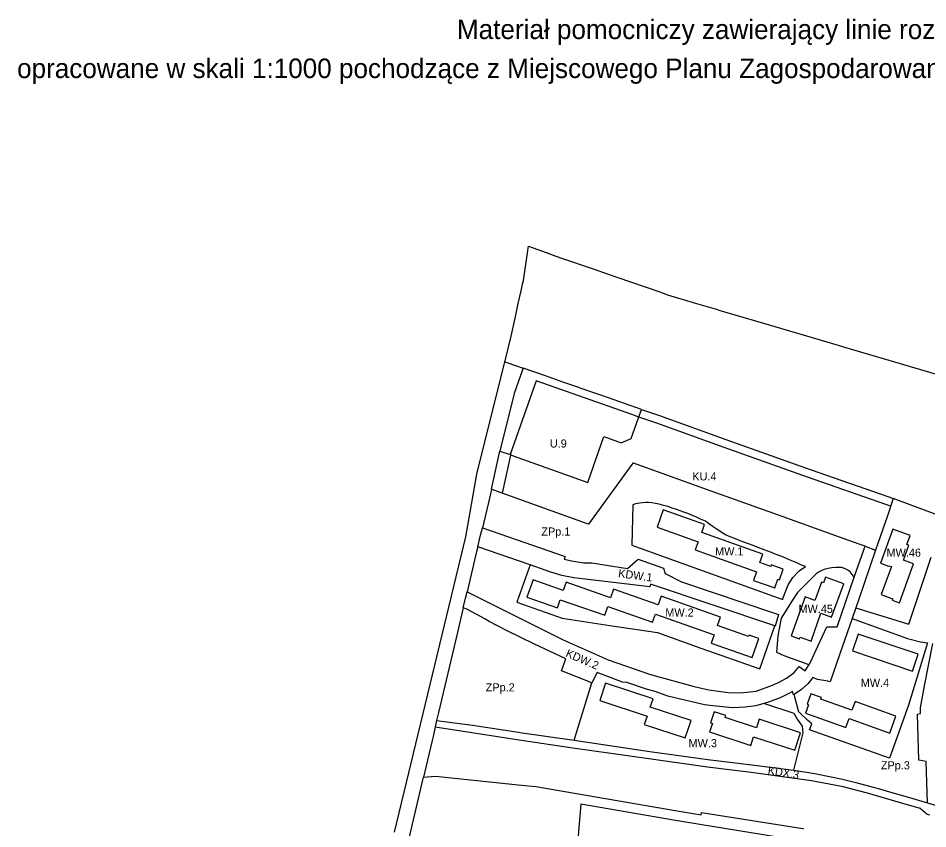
# Model space of a CAD drawing. Extents: x 7424434 to 7425898, y 5541432 to 5542659.
# Drawn here: x 7424434 to 7424994, y 5542160 to 5542659 of the extents above; entities that cross this region are included whole.
import ezdxf

# ---------------------------------------------------------------- set-up
doc = ezdxf.new("R2010")
doc.units = 0
for name, color, linetype in [('info', 7, 'Continuous'), ('linie rozgraniczające', 7, 'Continuous'), ('nieprzekraczalne linie zabudowy', 7, 'Continuous'), ('obowiazujace linie zabudowy', 7, 'Continuous'), ('przeznaczenia terenów', 7, 'Continuous')]:
    doc.layers.add(name, color=color, linetype=linetype)

msp = doc.modelspace()

# ---------------------------------------------------------------- linework, layer by layer
at = {"layer": 'linie rozgraniczające'}
for p, q in [((7424747.58, 5542514.42), (7424748.19, 5542518.62)), ((7424748.19, 5542518.62), (7424759.12, 5542514.54)), ((7424745.11, 5542497.46), (7424747.58, 5542514.42)), ((7424759.12, 5542514.54), (7424765.14, 5542512.45)), ((7424765.14, 5542512.45), (7424769.26, 5542511.04)), ((7424769.26, 5542511.04), (7424787.38, 5542504.79)), ((7424787.38, 5542504.79), (7424802.65, 5542499.52)), ((7424744.59, 5542495.06), (7424745.11, 5542497.46)), ((7424802.65, 5542499.52), (7424828.39, 5542490.65)), ((7424742.01, 5542483.22), (7424743.74, 5542491.15)), ((7424743.74, 5542491.15), (7424744.59, 5542495.06)), ((7424828.39, 5542490.65), (7424833.85, 5542488.62)), ((7424833.85, 5542488.62), (7424851.6, 5542483.34)), ((7424740.46, 5542476.12), (7424742.01, 5542483.22)), ((7424851.6, 5542483.34), (7424864.53, 5542479.49)), ((7424864.53, 5542479.49), (7424865.45, 5542479.21)), ((7424865.45, 5542479.21), (7424880.09, 5542474.94)), ((7424737.62, 5542463.08), (7424740.46, 5542476.12)), ((7424880.09, 5542474.94), (7424892.89, 5542471.2)), ((7424892.89, 5542471.2), (7424938.86, 5542457.56)), ((7424733.85, 5542447.88), (7424737.62, 5542463.08)), ((7424938.86, 5542457.56), (7424942.63, 5542456.45)), ((7424942.63, 5542456.45), (7424970.07, 5542448.41)), ((7424716.59, 5542378.26), (7424733.73, 5542447.39)), ((7424733.73, 5542447.39), (7424733.85, 5542447.88)), ((7424733.73, 5542447.39), (7424734.89, 5542447.02)), ((7424734.89, 5542447.02), (7424744.92, 5542443.52)), ((7424970.07, 5542448.41), (7425002.02, 5542438.91)), ((7424744.92, 5542443.52), (7424743.36, 5542439.03)), ((7424758.82, 5542438.66), (7424744.92, 5542443.52)), ((7424743.36, 5542439.03), (7424739.45, 5542427.79)), ((7424770.06, 5542434.73), (7424758.82, 5542438.66)), ((7424779.86, 5542431.31), (7424770.06, 5542434.73)), ((7424780.13, 5542431.21), (7424779.86, 5542431.31)), ((7424789.77, 5542427.86), (7424780.13, 5542431.21)), ((7424739.45, 5542427.79), (7424730.64, 5542392.38)), ((7424793.37, 5542426.6), (7424789.77, 5542427.86)), ((7424817.89, 5542418.07), (7424793.37, 5542426.6)), ((7424815.99, 5542412.83), (7424817.89, 5542418.07)), ((7424817.89, 5542418.07), (7424828.25, 5542414.47)), ((7424811.43, 5542400.27), (7424815.99, 5542412.83)), ((7424828.25, 5542414.47), (7424870.4, 5542399.4)), ((7424785.06, 5542373.76), (7424794.62, 5542401.34)), ((7424794.62, 5542401.34), (7424805.37, 5542397.43)), ((7424805.37, 5542397.43), (7424811.43, 5542400.27)), ((7424870.4, 5542399.4), (7424921.66, 5542381.02)), ((7424725.5, 5542369.02), (7424730.44, 5542391.58)), ((7424730.44, 5542391.58), (7424730.64, 5542392.38)), ((7424730.64, 5542392.38), (7424736.95, 5542390.25)), ((7424736.95, 5542390.25), (7424738.82, 5542389.58)), ((7424738.82, 5542389.58), (7424784.81, 5542373.04)), ((7424811.93, 5542384.28), (7424785.27, 5542347.42)), ((7424812.5, 5542385.08), (7424811.93, 5542384.28)), ((7424812.83, 5542384.96), (7424812.5, 5542385.08)), ((7424856.25, 5542369.41), (7424812.83, 5542384.96)), ((7424709.76, 5542339.63), (7424716.59, 5542378.26)), ((7424921.66, 5542381.02), (7424969.88, 5542364.28)), ((7424784.81, 5542373.04), (7424785.06, 5542373.76)), ((7424725.45, 5542368.81), (7424724.44, 5542364.19)), ((7424725.5, 5542369.02), (7424725.45, 5542368.81)), ((7424726.97, 5542368.48), (7424725.5, 5542369.02)), ((7424783.28, 5542348.14), (7424726.97, 5542368.48)), ((7424857.86, 5542368.83), (7424856.25, 5542369.41)), ((7424907.78, 5542350.95), (7424857.86, 5542368.83)), ((7424724.44, 5542364.19), (7424719.88, 5542345.25)), ((7424972.7, 5542363.24), (7424969.06, 5542352.6)), ((7424969.88, 5542364.28), (7424972.7, 5542363.24)), ((7425004.03, 5542351.55), (7424972.7, 5542363.24)), ((7424812.37, 5542359.37), (7424811.77, 5542334.52)), ((7424814.16, 5542359.9), (7424812.37, 5542359.37)), ((7424816.52, 5542360.41), (7424814.16, 5542359.9)), ((7424818.72, 5542360.67), (7424816.52, 5542360.41)), ((7424820.18, 5542360.76), (7424818.72, 5542360.67)), ((7424822.13, 5542360.73), (7424820.18, 5542360.76)), ((7424824.06, 5542360.62), (7424822.13, 5542360.73)), ((7424826.51, 5542360.28), (7424824.06, 5542360.62)), ((7424829.49, 5542359.64), (7424826.51, 5542360.28)), ((7424831.39, 5542359.05), (7424829.49, 5542359.64)), ((7424834.2, 5542358.25), (7424831.39, 5542359.05)), ((7424836.72, 5542357.36), (7424834.2, 5542358.25)), ((7424839.25, 5542356.48), (7424836.72, 5542357.36)), ((7424843.76, 5542354.95), (7424839.25, 5542356.48)), ((7424846.29, 5542354.05), (7424843.76, 5542354.95)), ((7424849.15, 5542352.78), (7424846.29, 5542354.05)), ((7424851.65, 5542351.72), (7424849.15, 5542352.78)), ((7424854.05, 5542350.62), (7424851.65, 5542351.72)), ((7424857.18, 5542349.25), (7424854.05, 5542350.62)), ((7424909.4, 5542350.37), (7424907.78, 5542350.95)), ((7424944.75, 5542337.7), (7424909.4, 5542350.37)), ((7424969.06, 5542352.6), (7424961.85, 5542331.57)), ((7424718.8, 5542340.75), (7424719.88, 5542345.25)), ((7424719.88, 5542345.25), (7424730.63, 5542341.51)), ((7424783.33, 5542348.12), (7424783.28, 5542348.14)), ((7424784.29, 5542347.77), (7424783.33, 5542348.12)), ((7424785.27, 5542347.42), (7424784.29, 5542347.77)), ((7424858.23, 5542348.53), (7424857.18, 5542349.25)), ((7424861.32, 5542346.31), (7424858.23, 5542348.53)), ((7424863.82, 5542344.63), (7424861.32, 5542346.31)), ((7424865.34, 5542343.48), (7424863.82, 5542344.63)), ((7424665.78, 5542157.87), (7424709.76, 5542339.63)), ((7424717.07, 5542333.55), (7424718.8, 5542340.75)), ((7424730.63, 5542341.51), (7424765.58, 5542329.35)), ((7424867.43, 5542342.16), (7424865.34, 5542343.48)), ((7424869.5, 5542340.96), (7424867.43, 5542342.16)), ((7424871.42, 5542340), (7424869.5, 5542340.96)), ((7424872.91, 5542339.45), (7424871.42, 5542340)), ((7424875.64, 5542338.43), (7424872.91, 5542339.45)), ((7424717.07, 5542333.55), (7424716.52, 5542331.25)), ((7424749.29, 5542322.4), (7424717.07, 5542333.55)), ((7424811.77, 5542334.52), (7424904.21, 5542301.36)), ((7424878.6, 5542337.31), (7424875.64, 5542338.43)), ((7424883.72, 5542335.35), (7424878.6, 5542337.31)), ((7424886.42, 5542334.35), (7424883.72, 5542335.35)), ((7424889, 5542333.41), (7424886.42, 5542334.35)), ((7424893.31, 5542331.75), (7424889, 5542333.41)), ((7424952.3, 5542335), (7424944.75, 5542337.7)), ((7424954.89, 5542334.07), (7424952.3, 5542335)), ((7424954.51, 5542331.64), (7424955.32, 5542333.92)), ((7424955.32, 5542333.92), (7424954.89, 5542334.07)), ((7424955.32, 5542333.92), (7424961.85, 5542331.57)), ((7424716.38, 5542330.68), (7424710.5, 5542305.82)), ((7424716.52, 5542331.25), (7424716.38, 5542330.68)), ((7424765.58, 5542329.35), (7424770.74, 5542327.55)), ((7424770.74, 5542327.55), (7424770.22, 5542325.99)), ((7424897.77, 5542330.05), (7424893.31, 5542331.75)), ((7424900.1, 5542329.11), (7424897.77, 5542330.05)), ((7424904.08, 5542327.49), (7424900.1, 5542329.11)), ((7424908.95, 5542325.47), (7424904.08, 5542327.49)), ((7424948.74, 5542314.81), (7424954.51, 5542331.64)), ((7424961.85, 5542331.57), (7424951.28, 5542300.72)), ((7424749.29, 5542322.4), (7424741.13, 5542299.47)), ((7424761.92, 5542318.01), (7424749.29, 5542322.4)), ((7424770.22, 5542325.99), (7424774.79, 5542324.89)), ((7424774.79, 5542324.89), (7424782.27, 5542323.72)), ((7424782.27, 5542323.72), (7424787.31, 5542323.7)), ((7424787.31, 5542323.7), (7424809.18, 5542320.26)), ((7424809.18, 5542320.26), (7424815.66, 5542325.84)), ((7424815.66, 5542325.84), (7424831.34, 5542320.35)), ((7424912.71, 5542323.87), (7424908.95, 5542325.47)), ((7424914.19, 5542323.28), (7424912.71, 5542323.87)), ((7424916.31, 5542322.24), (7424914.19, 5542323.28)), ((7424918.72, 5542321.43), (7424916.31, 5542322.24)), ((7424982.33, 5542285.97), (7424995.99, 5542327.25)), ((7424768.75, 5542315.92), (7424761.92, 5542318.01)), ((7424831.34, 5542320.35), (7424832.45, 5542317.04)), ((7424832.45, 5542317.04), (7424842.51, 5542312.06)), ((7424910.81, 5542314.65), (7424914.87, 5542318.8)), ((7424925.23, 5542316.81), (7424913.74, 5542305.44)), ((7424914.87, 5542318.8), (7424918.72, 5542321.43)), ((7424927.03, 5542318.18), (7424925.23, 5542316.81)), ((7424928.28, 5542318.75), (7424927.03, 5542318.18)), ((7424930.22, 5542319.5), (7424928.28, 5542318.75)), ((7424932.68, 5542320.11), (7424930.22, 5542319.5)), ((7424933.67, 5542320.42), (7424932.68, 5542320.11)), ((7424934.96, 5542320.66), (7424933.67, 5542320.42)), ((7424937.35, 5542320.77), (7424934.96, 5542320.66)), ((7424939, 5542320.84), (7424937.35, 5542320.77)), ((7424940.76, 5542320.71), (7424939, 5542320.84)), ((7424942.69, 5542320.13), (7424940.76, 5542320.71)), ((7424944.77, 5542319.17), (7424942.69, 5542320.13)), ((7424946.27, 5542318.18), (7424944.77, 5542319.17)), ((7424948.74, 5542314.81), (7424946.27, 5542318.18)), ((7424776.16, 5542314.52), (7424768.75, 5542315.92)), ((7424786.7, 5542313.19), (7424776.16, 5542314.52)), ((7424822.87, 5542308.89), (7424786.7, 5542313.19)), ((7424842.51, 5542312.06), (7424899.04, 5542292.89)), ((7424908.09, 5542310.13), (7424910.81, 5542314.65)), ((7424938.26, 5542284.22), (7424948.74, 5542314.81)), ((7424709.57, 5542301.88), (7424710.5, 5542305.82)), ((7424710.5, 5542305.82), (7424738.45, 5542291.93)), ((7424823.43, 5542310.56), (7424822.87, 5542308.89)), ((7424899.92, 5542284.87), (7424823.43, 5542310.56)), ((7424904.8, 5542301.67), (7424908.09, 5542310.13)), ((7424913.74, 5542305.44), (7424910.24, 5542300.08)), ((7424708.17, 5542295.94), (7424709.57, 5542301.88)), ((7424741.13, 5542299.47), (7424769.09, 5542289.67)), ((7424910.24, 5542300.08), (7424903.72, 5542289.61)), ((7424904.21, 5542301.36), (7424904.67, 5542301.2)), ((7424904.67, 5542301.2), (7424904.8, 5542301.67)), ((7424951.28, 5542300.72), (7424949.67, 5542296.03)), ((7424708.17, 5542295.94), (7424706.73, 5542289.82)), ((7424710.25, 5542295.16), (7424708.17, 5542295.94)), ((7424721.39, 5542289.12), (7424710.25, 5542295.16)), ((7424949.67, 5542296.03), (7424947.43, 5542289.48)), ((7424949.67, 5542296.03), (7424961.46, 5542292.39)), ((7424706.73, 5542289.82), (7424705.06, 5542282.73)), ((7424724.17, 5542287.61), (7424721.39, 5542289.12)), ((7424738.45, 5542291.93), (7424769.69, 5542276.4)), ((7424769.09, 5542289.67), (7424798.26, 5542285.03)), ((7424899.04, 5542292.89), (7424902.06, 5542291.87)), ((7424902.06, 5542291.87), (7424900.09, 5542284.81)), ((7424903.72, 5542289.61), (7424901.64, 5542278.86)), ((7424947.43, 5542289.48), (7424939.85, 5542267.76)), ((7424947.43, 5542289.48), (7424981.55, 5542277.21)), ((7424961.46, 5542292.39), (7424982.33, 5542285.97)), ((7424705.06, 5542282.73), (7424704.41, 5542279.97)), ((7424734.74, 5542282.13), (7424724.17, 5542287.61)), ((7424798.26, 5542285.03), (7424827.65, 5542280.81)), ((7424890.63, 5542258.42), (7424899.92, 5542284.87)), ((7424900.09, 5542284.81), (7424899.92, 5542284.87)), ((7424926.45, 5542272.78), (7424931.82, 5542284.27)), ((7424931.82, 5542284.27), (7424938.26, 5542284.22)), ((7424704.41, 5542279.97), (7424692.91, 5542231.55)), ((7424751.96, 5542273.59), (7424734.74, 5542282.13)), ((7424827.65, 5542280.81), (7424854.29, 5542271.15)), ((7424901.64, 5542278.86), (7424900.89, 5542268.69)), ((7424981.55, 5542277.21), (7424989.37, 5542275.1)), ((7424771.27, 5542264.57), (7424751.96, 5542273.59)), ((7424769.69, 5542276.4), (7424797.3, 5542264.07)), ((7424921.76, 5542262.51), (7424926.45, 5542272.78)), ((7424993.68, 5542274.53), (7424981.97, 5542236.08)), ((7424989.37, 5542275.1), (7424993.68, 5542274.53)), ((7424991.92, 5542247.99), (7424997.06, 5542274.09)), ((7424854.29, 5542271.15), (7424890.63, 5542258.42)), ((7424900.89, 5542268.69), (7424905.38, 5542266.6)), ((7424905.38, 5542266.6), (7424920.06, 5542261.4)), ((7424939.85, 5542267.76), (7424933.97, 5542250.37)), ((7424768.64, 5542257.3), (7424771.27, 5542264.57)), ((7424797.3, 5542264.07), (7424823.41, 5542255.06)), ((7424918.53, 5542257.14), (7424920.95, 5542261.17)), ((7424920.06, 5542261.4), (7424920.95, 5542261.17)), ((7424920.95, 5542261.17), (7424921.76, 5542262.51)), ((7424787.32, 5542249.76), (7424768.64, 5542257.3)), ((7424790.42, 5542256.29), (7424787.32, 5542249.76)), ((7424806.05, 5542250.28), (7424790.42, 5542256.29)), ((7424823.41, 5542255.06), (7424850.23, 5542247.49)), ((7424907.06, 5542252.81), (7424911.72, 5542256.3)), ((7424911.72, 5542256.3), (7424914.76, 5542259.99)), ((7424914.76, 5542259.99), (7424918.53, 5542257.14)), ((7424776.27, 5542214.49), (7424787.32, 5542249.76)), ((7424808.77, 5542249.97), (7424806.05, 5542250.28)), ((7424821.43, 5542245.84), (7424808.77, 5542249.97)), ((7424898.47, 5542248.36), (7424902.07, 5542249.98)), ((7424902.07, 5542249.98), (7424907.06, 5542252.81)), ((7424920.12, 5542249.27), (7424916.26, 5542245.71)), ((7424923.25, 5542253.07), (7424920.12, 5542249.27)), ((7424926.01, 5542251.91), (7424923.25, 5542253.07)), ((7424932.38, 5542250.93), (7424926.01, 5542251.91)), ((7424933.97, 5542250.37), (7424932.38, 5542250.93)), ((7424826.25, 5542244.46), (7424821.43, 5542245.84)), ((7424834.08, 5542241.6), (7424826.25, 5542244.46)), ((7424850.23, 5542247.49), (7424859.15, 5542245.44)), ((7424859.15, 5542245.44), (7424871.18, 5542243.86)), ((7424871.18, 5542243.86), (7424878.75, 5542243.62)), ((7424878.75, 5542243.62), (7424888.42, 5542244.73)), ((7424888.42, 5542244.73), (7424898.47, 5542248.36)), ((7424909.28, 5542243.6), (7424906.35, 5542242.25)), ((7424910.62, 5542244.53), (7424909.28, 5542243.6)), ((7424911.24, 5542242.4), (7424910.62, 5542244.53)), ((7424916.26, 5542245.71), (7424911.66, 5542242.68)), ((7424989.5, 5542234.42), (7424991.92, 5542247.99)), ((7424856.49, 5542236.32), (7424834.08, 5542241.6)), ((7424903.14, 5542240.71), (7424895.88, 5542237.89)), ((7424906.35, 5542242.25), (7424903.14, 5542240.71)), ((7424911.66, 5542242.68), (7424911.24, 5542242.4)), ((7424914.68, 5542231.77), (7424911.66, 5542242.68)), ((7424863.77, 5542235.49), (7424856.49, 5542236.32)), ((7424873.7, 5542234.51), (7424863.77, 5542235.49)), ((7424881.61, 5542234.81), (7424873.7, 5542234.51)), ((7424888.09, 5542235.78), (7424881.61, 5542234.81)), ((7424892.98, 5542237.1), (7424888.09, 5542235.78)), ((7424895.88, 5542237.89), (7424892.98, 5542237.1)), ((7424911.74, 5542230.97), (7424892.98, 5542237.1)), ((7424981.97, 5542236.08), (7424970.33, 5542203.42)), ((7424989.5, 5542230.98), (7424989.5, 5542234.42)), ((7424692.91, 5542231.55), (7424691.75, 5542226.67)), ((7424913.36, 5542228.15), (7424911.74, 5542230.97)), ((7424913.46, 5542227.99), (7424913.36, 5542228.15)), ((7424913.79, 5542227.41), (7424913.46, 5542227.99)), ((7424916.87, 5542223.11), (7424913.79, 5542227.41)), ((7424915.18, 5542231.4), (7424914.68, 5542231.77)), ((7424919.97, 5542226.91), (7424915.18, 5542231.4)), ((7424922.51, 5542224.54), (7424919.97, 5542226.91)), ((7424987.53, 5542230.58), (7424989.5, 5542230.98)), ((7424988.37, 5542202.28), (7424987.53, 5542230.58)), ((7424690.85, 5542222.85), (7424689.55, 5542216.85)), ((7424691.75, 5542226.67), (7424690.85, 5542222.85)), ((7424690.85, 5542222.85), (7424713.32, 5542219.34)), ((7424691.75, 5542226.67), (7424713.85, 5542223.78)), ((7424713.85, 5542223.78), (7424742.15, 5542219.4)), ((7424917.33, 5542218.98), (7424916.87, 5542223.11)), ((7424921.15, 5542220.87), (7424922.51, 5542224.54)), ((7424689.55, 5542216.85), (7424688.74, 5542213.53)), ((7424713.32, 5542219.34), (7424742.51, 5542214.77)), ((7424742.15, 5542219.4), (7424743.04, 5542219.26)), ((7424743.04, 5542219.26), (7424776.27, 5542214.49)), ((7424911.52, 5542196.1), (7424917.33, 5542218.98)), ((7424970.33, 5542203.42), (7424921.15, 5542220.87)), ((7424688.74, 5542213.53), (7424683.68, 5542191.73)), ((7424742.51, 5542214.77), (7424775.52, 5542209.94)), ((7424775.52, 5542209.94), (7424822.27, 5542203.18)), ((7424776.27, 5542214.49), (7424822.85, 5542207.68)), ((7424822.85, 5542207.68), (7424858.56, 5542202.71)), ((7424822.27, 5542203.18), (7424858.4, 5542198.14)), ((7424858.56, 5542202.71), (7424885.77, 5542199.33)), ((7424885.77, 5542199.33), (7424911.52, 5542196.1)), ((7424993, 5542201.41), (7424988.37, 5542202.28)), ((7424993.72, 5542175.99), (7424993, 5542201.41)), ((7424858.4, 5542198.14), (7424885.22, 5542194.8)), ((7424885.22, 5542194.8), (7424922.46, 5542189.82)), ((7424911.52, 5542196.1), (7424919.35, 5542194.89)), ((7424919.35, 5542194.89), (7424925.55, 5542193.87)), ((7424925.55, 5542193.87), (7424933.46, 5542192.18)), ((7424674.48, 5542152.32), (7424683.68, 5542191.73)), ((7424683.68, 5542191.73), (7424691.14, 5542192.38)), ((7424691.14, 5542192.38), (7424744.06, 5542186.89)), ((7424922.46, 5542189.82), (7424940.84, 5542186.25)), ((7424933.46, 5542192.18), (7424941.37, 5542190.48)), ((7424941.37, 5542190.48), (7424949.74, 5542188.41)), ((7424949.74, 5542188.41), (7424958.1, 5542186.33)), ((7424744.06, 5542186.89), (7424752.69, 5542186)), ((7424752.69, 5542186), (7424839.76, 5542171)), ((7424940.84, 5542186.25), (7424956.55, 5542182.15)), ((7424956.55, 5542182.15), (7424980.38, 5542175.26)), ((7424958.1, 5542186.33), (7424964.24, 5542184.59)), ((7424964.24, 5542184.59), (7424970.37, 5542182.85)), ((7424970.37, 5542182.85), (7424981.19, 5542179.67)), ((7424981.19, 5542179.67), (7424993.72, 5542175.99)), ((7424839.76, 5542171), (7424854.55, 5542168.59)), ((7424980.38, 5542175.26), (7424989.32, 5542172.68)), ((7424989.32, 5542172.68), (7424993.48, 5542169.09)), ((7424993.72, 5542175.99), (7425003.48, 5542173.11)), ((7424854.55, 5542168.59), (7424854.67, 5542169.96)), ((7424854.67, 5542169.96), (7424917.08, 5542160.2)), ((7424993.48, 5542169.09), (7424995.11, 5542168.64)), ((7424917.08, 5542160.2), (7424917.55, 5542159.83))]:
    msp.add_line(p, q, dxfattribs=at)
at = {"layer": 'nieprzekraczalne linie zabudowy'}
for points in [[(7424816.19, 5542413.4), (7424812.45, 5542414.72), (7424752.92, 5542435.68), (7424736.95, 5542390.25)], [(7424970.97, 5542358.55), (7424968.2, 5542359.57), (7424920, 5542376.3), (7424868.72, 5542394.69), (7424826.59, 5542409.75), (7424816.25, 5542413.35)], [(7424737.43, 5542390.68), (7424737.26, 5542389.98), (7424732.14, 5542366.62)]]:
    msp.add_lwpolyline(points, dxfattribs=at)
msp.add_lwpolyline([(7424910.57, 5542153.41), (7424853.59, 5542162.67), (7424838.77, 5542165.08), (7424780.57, 5542175.11), (7424771.38, 5542068.74), (7424791.79, 5542066.66), (7424797.38, 5542066.09), (7424845.66, 5542061.44), (7424898.44, 5542056.38), (7424903.72, 5542105.59)], close=True, dxfattribs=at)
at = {"layer": 'obowiazujace linie zabudowy'}
for points in [[(7424831.13, 5542356.23), (7424827.35, 5542345.62), (7424852.68, 5542336.61), (7424850.9, 5542331.61), (7424888.64, 5542318.19), (7424886.75, 5542312.89), (7424899.82, 5542308.25), (7424901.71, 5542313.57), (7424902.67, 5542313.23), (7424904.99, 5542319.74), (7424897.65, 5542322.35), (7424897.33, 5542321.46), (7424890.69, 5542323.83), (7424892.5, 5542328.94), (7424854.87, 5542342.32), (7424856.62, 5542347.33)], [(7424964.94, 5542323.38), (7424969.75, 5542321.68), (7424969.83, 5542321.92), (7424971.54, 5542321.35), (7424965.25, 5542304.18), (7424971.17, 5542302.01), (7424972.4, 5542301.56), (7424972.07, 5542300.65), (7424976.6, 5542299.03), (7424985.23, 5542323.15), (7424978.94, 5542325.4), (7424982.21, 5542334.54), (7424981.09, 5542334.94), (7424983.07, 5542340.55), (7424972.35, 5542344.34)], [(7424751.07, 5542313.21), (7424747.35, 5542302.59), (7424766.03, 5542296.04), (7424767.78, 5542301.01), (7424795.19, 5542291.4), (7424797.09, 5542296.83), (7424824.59, 5542287.18), (7424826.31, 5542292.08), (7424862.49, 5542279.39), (7424860.67, 5542274.21), (7424885.95, 5542265.34), (7424890.08, 5542277.1), (7424883.96, 5542279.25), (7424883.66, 5542278.39), (7424864.65, 5542285.06), (7424866.48, 5542290.29), (7424829.93, 5542303.12), (7424828.04, 5542297.74), (7424800.53, 5542307.39), (7424798.7, 5542302.16), (7424771.45, 5542311.72), (7424769.67, 5542306.66)], [(7424918.5, 5542302.74), (7424909.84, 5542278.82), (7424914.96, 5542276.97), (7424915.34, 5542278.01), (7424916.55, 5542277.57), (7424922.21, 5542275.52), (7424928.1, 5542292.7), (7424934.76, 5542290.22), (7424942.29, 5542310.85), (7424931.1, 5542314.91), (7424929.78, 5542311.36), (7424928.57, 5542311.75), (7424925.59, 5542303.69), (7424924.46, 5542300.58)], [(7424951.08, 5542279.84), (7424947.57, 5542269.46), (7424984.43, 5542257), (7424987.94, 5542267.38)], [(7424795.71, 5542249.67), (7424792.18, 5542239.03), (7424821.22, 5542229.4), (7424819.53, 5542224.3), (7424844.76, 5542215.93), (7424848.3, 5542226.6), (7424823.23, 5542234.91), (7424824.91, 5542240)], [(7424943.52, 5542222.28), (7424945.51, 5542227.85), (7424970.55, 5542218.92), (7424974.28, 5542229.39), (7424949.16, 5542238.34), (7424947.23, 5542232.92), (7424928.06, 5542239.75), (7424928.46, 5542240.88), (7424922.01, 5542243.17), (7424919.68, 5542236.64), (7424920.62, 5542236.3), (7424918.77, 5542231.1)], [(7424885.03, 5542211.37), (7424886.74, 5542216.6), (7424912.1, 5542208.31), (7424915.65, 5542219.17), (7424890.27, 5542227.47), (7424888.53, 5542222.16), (7424869.33, 5542228.44), (7424869.73, 5542229.67), (7424862.42, 5542232.06), (7424860.18, 5542225.21), (7424861.42, 5542224.81), (7424859.73, 5542219.64)]]:
    msp.add_lwpolyline(points, close=True, dxfattribs=at)

# ---------------------------------------------------------------- texts
at = {"layer": 'info'}
for s, p in [('Materiał pomocniczy zawierający linie rozgraniczające teren o różnym przeznaczeniu i różnych warunkach zagospodarowania terenu, ', (7424704.25, 5542645.97)), ('opracowane w skali 1:1000 pochodzące z Miejscowego Planu Zagospodarowania Przestrzennego obszaru "OSIEDLE KURDWANÓW" zatwierdzonego uchwałą RMK Nr LXXIX/1938/17 z dnia 5 lipca 2017 r.', (7424433.64, 5542621.97))]:
    msp.add_text(s, height=12, dxfattribs=at).set_placement(p)
at = {"layer": 'przeznaczenia terenów'}
for s, p in [('U.9', (7424761.42, 5542394.62)), ('KU.4', (7424849.06, 5542374.4)), ('ZPp.1', (7424756.2, 5542340.43)), ('MW.1', (7424863.05, 5542328.23)), ('MW.46', (7424968.56, 5542327.44)), ('MW.2', (7424832.45, 5542290.59)), ('MW.45', (7424914.39, 5542292.85)), ('ZPp.2', (7424721.96, 5542244.57)), ('MW.4', (7424952.7, 5542247.37)), ('MW.3', (7424846.75, 5542210.24)), ('ZPp.3', (7424965.05, 5542196.59))]:
    msp.add_text(s, height=5, dxfattribs=at).set_placement(p)
for s, rotation, p in [('KDW.1', 352.4712, (7424803.24, 5542314.89)), ('KDW.2', 336.6252, (7424770.71, 5542266.2)), ('KDX.3', 350.9031, (7424895.22, 5542193.66))]:
    msp.add_text(s, height=5, rotation=rotation, dxfattribs=at).set_placement(p)

doc.saveas('drawing.dxf')
